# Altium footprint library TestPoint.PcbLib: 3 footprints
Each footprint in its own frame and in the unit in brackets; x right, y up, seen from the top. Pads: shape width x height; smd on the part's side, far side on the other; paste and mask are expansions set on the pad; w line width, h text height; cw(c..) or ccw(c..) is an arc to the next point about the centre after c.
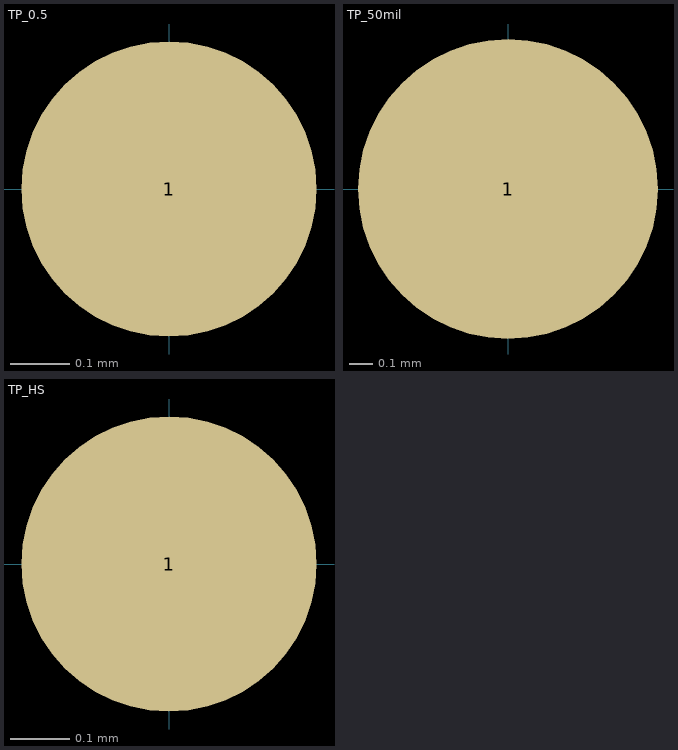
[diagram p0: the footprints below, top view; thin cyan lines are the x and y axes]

## TP_0.5 [mm]
pads (1):
  round 0.5 smd mask+0.05: 1(0,0)

## TP_50mil [mm]
pads (1):
  round 1.27 smd mask+0.05: 1(0,0)

## TP_HS [mm]
pads (1):
  round 0.5 smd mask+0.05: 1(0,0)
Layer 1:
  pour cut-out: 0,0.254 0.051,0.254 0.144,0.215 0.215,0.144 0.254,0.051 0.254,0 0.254,-0.051 0.215,-0.144 0.144,-0.215 0.051,-0.254 0,-0.254 -0.051,-0.254 -0.144,-0.215 -0.215,-0.144 -0.254,-0.051 -0.254,0 -0.254,0.051 -0.215,0.144 -0.144,0.215 -0.051,0.254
